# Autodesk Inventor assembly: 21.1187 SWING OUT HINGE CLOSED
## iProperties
Created: 2007-07
Part Number: 21.1187 SWING OUT HINGE CLOSED
Document SubType Name: Assembly
Designer: Andy Moles
Author: Andy Moles
